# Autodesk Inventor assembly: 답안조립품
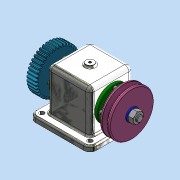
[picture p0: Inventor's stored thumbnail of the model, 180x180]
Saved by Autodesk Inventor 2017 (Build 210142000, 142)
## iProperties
Part Number: 답안조립품
Material: 일반
Document SubType Name: Assembly
Designer: MRC
Author: MRC
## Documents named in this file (12)
- C:\Users\MRC\Desktop\720706V1015\답안조립품.iam
- C:\Users\MRC\Desktop\720706V1015\V벨트풀리.ipt
- C:\Users\MRC\Desktop\720706V1015\너트 M12x1.25.ipt
- C:\Users\MRC\Desktop\720706V1015\베어링 6204.ipt
- C:\Users\MRC\Desktop\720706V1015\본체.ipt
- C:\Users\MRC\Desktop\720706V1015\볼트 M4x0.7.ipt
- C:\Users\MRC\Desktop\720706V1015\스퍼기어.ipt
- C:\Users\MRC\Desktop\720706V1015\오일실 20x35x8.ipt
- C:\Users\MRC\Desktop\720706V1015\와셔 12x24.ipt
- C:\Users\MRC\Desktop\720706V1015\축.ipt
- C:\Users\MRC\Desktop\720706V1015\커버.ipt
- C:\Users\MRC\Desktop\720706V1015\키 5x5.ipt
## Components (1 placed, 1 different names)
1. V벨트풀리:2
